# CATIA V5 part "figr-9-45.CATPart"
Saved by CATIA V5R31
Part number: Part1
Bounding box of the stored display mesh (mm): x -159.661 to 182.627, y -78.048 to 78.048, z 0 to 72.429
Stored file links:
  D:\PROJECTS\Project 2021\US EDITION\CATIA V5 6R 2021\Resources\Part Files\c09_catia_v5_6r2021_prt\c09_catia_v5_6r2021_prt\figr-9-45.CATPart
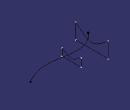
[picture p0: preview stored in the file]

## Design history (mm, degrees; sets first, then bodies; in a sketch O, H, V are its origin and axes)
Body1 (main body)
  Plane1: type Offset, RefPlane yz-plane, Offset 100
  Plane2: type Offset, RefPlane yz-plane, Offset 100, reversed
  Sketch1 on Plane1, origin (100, 0, 0), H (0, 1, 0), V (0, 0, 1)
    point P1 (0, 15.965)
    hyperbola C1
    point P2 (0, 3.0416)
    line L1 (54.8261, 44.8858) -> (54.8261, 0)
    point P5 (54.8261, 0)
    line L2 (-54.8261, 44.8858) -> (-54.8261, 0)
    point P6 (-54.8261, 0)
    line L3 (-54.8261, 0) -> (54.8261, 0)
    coincidence: P1 V, P2 V, P5 H, P6 H
    vertical: L1 V, L2 V
    horizontal: L3 H
  Sketch2 on xy-plane, origin (0, 0, 0), H (1, 0, 0), V (0, 1, 0)
    spline S1 through (-159.6608, -77.1468) (-77.8466, -31.8169) (23.6283, -41.4968) (182.6271, -11.7333)
  Sketch3 on yz-plane, origin (0, 0, 0), H (0, 1, 0), V (0, 0, 1)
    point P1 (0, 18.9787)
    hyperbola C1
    point P2 (0, 2.6681)
    line L1 (48.2237, 37.1764) -> (48.2237, 0)
    point P5 (48.2237, 0)
    line L2 (-43.6563, 34.1546) -> (-43.6563, 0)
    point P6 (-43.6563, 0)
    line L3 (-43.6563, 0) -> (48.2237, 0)
    coincidence: P1 V, P2 V, P5 H, P6 H
    vertical: L1 V, L2 V
    horizontal: L3 H
  Sketch4 on Plane2, origin (-100, 0, 0), H (0, 1, 0), V (0, 0, 1)
    point P1 (0, 140.6052)
    point P2 (0, 41.8972)
    hyperbola C1
    line L1 (78.0478, 72.4293) -> (78.0478, 0)
    point P5 (78.0478, 0)
    line L2 (-78.0478, 72.4293) -> (-78.0478, 0)
    point P6 (-78.0478, 0)
    line L3 (-78.0478, 0) -> (78.0478, 0)
    coincidence: P1 V, P2 V, P5 H, P6 H
    vertical: L1 V, L2 V
    horizontal: L3 H
  Loft1: solid, Sections (Sketch3; Sketch4), Spine Sketch2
